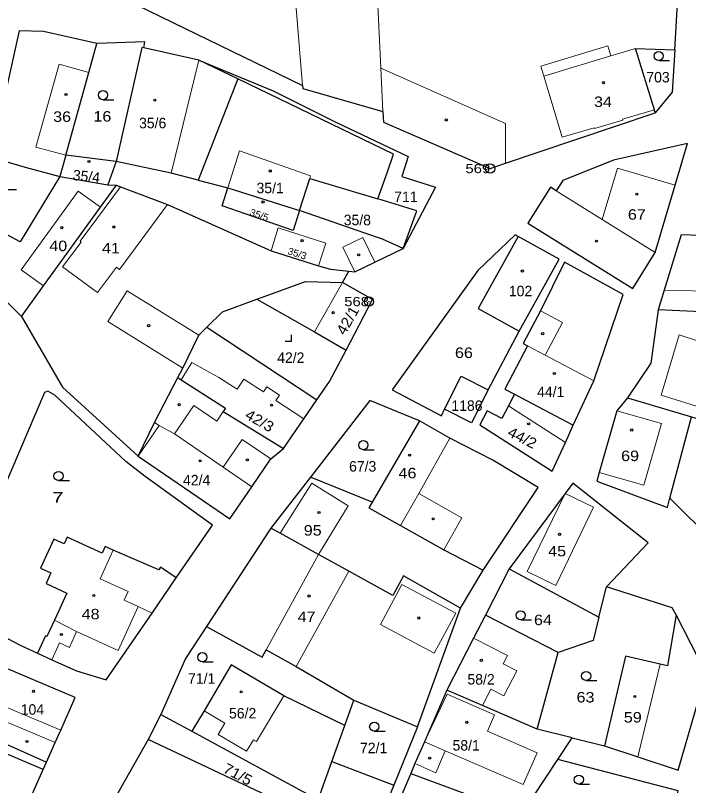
# Model space of a CAD drawing. Extents: x -758887 to -754328, y -1031688 to -1029144.
# Drawn here: x -756515.3 to -756406, y -1030560.6 to -1030435.5 of the extents above; entities that cross this region are included whole.
import ezdxf
from ezdxf.enums import TextEntityAlignment as Align

# ---------------------------------------------------------------- set-up
doc = ezdxf.new("R2010")
doc.units = 0
doc.header["$LTSCALE"] = 0.68
for name, color, linetype, lineweight in [('1', 7, 'Continuous', 25), ('3', 7, 'Continuous', 25), ('4', 7, 'Continuous', 13), ('5', 7, 'Continuous', 25), ('8', 7, 'Continuous', 25)]:
    doc.layers.add(name, color=color, linetype=linetype, lineweight=lineweight)
doc.layers.add('2', color=7, linetype='Continuous')

msp = doc.modelspace()

# ---------------------------------------------------------------- linework, layer by layer
at = {"layer": '1'}
for p, q in [((-756479.24, -1030445.82), (-756485.68, -1030462.26)), ((-756508.15, -1030461.68), (-756500.31, -1030462.99)), ((-756484.24, -1030486.15), (-756466.38, -1030497.95)), ((-756438.56, -1030496.32), (-756433.52, -1030486.81)), ((-756434.29, -1030497.04), (-756424.76, -1030502.04)), ((-756409.04, -1030513.92), (-756405.56, -1030500.72)), ((-756443.05, -1030531.77), (-756439.39, -1030525.61)), ((-756435.14, -1030525.41), (-756439.01, -1030532.91)), ((-756461.87, -1030550.85), (-756460.39, -1030546.71)), ((-756491.72, -1030549.05), (-756493.78, -1030553.1)), ((-756450.04, -1030551.07), (-756453.91, -1030560.56)), ((-756467.23, -1030565.61), (-756493.78, -1030553.1)), ((-756424.9, -1030552.84), (-756419.67, -1030554.14)), ((-756510.82, -1030558), (-756510.29, -1030556.81)), ((-756463.96, -1030556.71), (-756453.91, -1030560.56)), ((-756451.15, -1030558.65), (-756454.23, -1030565.79))]:
    msp.add_line(p, q, dxfattribs=at)
for points in [[(-756408.26, -1030441.06), (-756407.42, -1030426.91), (-756407.17, -1030422.67)], [(-756510.06, -1030431.65), (-756502.06, -1030431), (-756501.36, -1030430.94), (-756468.7, -1030446.88), (-756468.66, -1030447.38), (-756455.66, -1030451.12), (-756455.58, -1030452.82), (-756438.25, -1030460.37), (-756435.76, -1030459.47), (-756424.35, -1030455.63), (-756411.42, -1030451.34)], [(-756502.12, -1030440.04), (-756510.76, -1030438.1), (-756514.76, -1030437.98), (-756519.35, -1030458.53)], [(-756494.51, -1030440.77), (-756494.32, -1030439.78), (-756502.12, -1030440.04)], [(-756507.18, -1030458.21), (-756503.44, -1030444.77), (-756502.12, -1030440.04)], [(-756494.51, -1030440.77), (-756494.8, -1030440.7), (-756498.97, -1030459.24)], [(-756479.24, -1030445.82), (-756485.55, -1030442.78), (-756494.51, -1030440.77)], [(-756411.42, -1030451.34), (-756411.57, -1030450.84), (-756414.63, -1030440.87), (-756408.26, -1030441.06)], [(-756408.26, -1030441.06), (-756408.67, -1030447.94), (-756411.42, -1030451.34)], [(-756485.55, -1030442.78), (-756473.5, -1030447.72), (-756463.29, -1030452.83), (-756451.58, -1030458.43), (-756452.6, -1030461.64), (-756447.12, -1030463.38), (-756452.38, -1030473.38)], [(-756456.49, -1030465.29), (-756454.94, -1030460.89), (-756453.94, -1030458.02), (-756479.24, -1030445.82)], [(-756519.35, -1030458.53), (-756513.77, -1030460.12), (-756508.15, -1030461.68)], [(-756498.97, -1030459.24), (-756507.18, -1030458.21), (-756508.15, -1030461.68)], [(-756485.68, -1030462.26), (-756490.05, -1030461.14), (-756498.97, -1030459.24), (-756500.31, -1030462.99), (-756498.95, -1030463.07)], [(-756508.15, -1030461.68), (-756514.57, -1030472.26), (-756518.98, -1030469.92), (-756522.95, -1030467.81)], [(-756485.68, -1030462.26), (-756480.83, -1030463.51), (-756469.2, -1030467.18)], [(-756469.2, -1030467.18), (-756467.53, -1030461.96), (-756456.49, -1030465.29)], [(-756514.38, -1030484.42), (-756510.77, -1030479.43), (-756501.53, -1030466.64), (-756498.95, -1030463.07)], [(-756498.95, -1030463.07), (-756498.25, -1030463.33), (-756490.65, -1030466.23), (-756473.82, -1030473.71), (-756466.1, -1030476.17), (-756464.15, -1030476.71), (-756461.19, -1030477.06)], [(-756469.2, -1030467.18), (-756470.24, -1030470.42), (-756481.76, -1030466.45), (-756480.83, -1030463.51)], [(-756452.38, -1030473.38), (-756450.13, -1030467.23), (-756456.49, -1030465.29)], [(-756452.38, -1030473.38), (-756455.72, -1030471.84), (-756458.44, -1030470.9), (-756469.2, -1030467.18)], [(-756522.95, -1030467.81), (-756526.37, -1030474.26), (-756522.4, -1030476.37), (-756514.38, -1030484.42)], [(-756433.68, -1030471.41), (-756434.18, -1030471.13), (-756440.26, -1030476.91), (-756454.15, -1030496.31), (-756446.16, -1030500.53), (-756445.63, -1030499.48)], [(-756375.85, -1030484.87), (-756388.84, -1030471.72), (-756397.68, -1030471.45), (-756407.23, -1030471.16), (-756409.98, -1030480.1), (-756410.97, -1030483.3)], [(-756433.68, -1030471.41), (-756440.17, -1030483.13), (-756433.52, -1030486.81)], [(-756433.52, -1030486.81), (-756427.03, -1030475.09), (-756433.68, -1030471.41)], [(-756461.19, -1030477.06), (-756460.21, -1030477.17), (-756456.97, -1030475.6), (-756452.38, -1030473.38)], [(-756424.76, -1030502.04), (-756421.43, -1030494.83), (-756416.62, -1030480.84), (-756426.15, -1030475.57), (-756430.07, -1030483.48), (-756432.88, -1030488.78), (-756432.16, -1030489.16), (-756435.88, -1030496.2), (-756434.29, -1030497.04)], [(-756476.13, -1030481.61), (-756468.22, -1030478.73), (-756462.22, -1030478.88), (-756461.19, -1030477.06)], [(-756461.65, -1030489.85), (-756457.34, -1030481.66), (-756462.22, -1030478.88)], [(-756484.24, -1030486.15), (-756481.7, -1030483.64), (-756476.13, -1030481.61)], [(-756476.13, -1030481.61), (-756466.79, -1030486.92), (-756461.65, -1030489.85)], [(-756384.93, -1030481.41), (-756388.28, -1030481.31), (-756388.37, -1030484.34), (-756399.29, -1030483.84), (-756410.97, -1030483.3)], [(-756410.97, -1030483.3), (-756412.16, -1030491.99), (-756415.96, -1030497.63), (-756405.56, -1030500.72), (-756392.11, -1030504.7)], [(-756514.38, -1030484.42), (-756507.71, -1030495.87), (-756495.38, -1030507.08)], [(-756488.98, -1030494.33), (-756488.16, -1030492.77), (-756485.56, -1030487.45), (-756484.24, -1030486.15)], [(-756466.38, -1030497.95), (-756464.32, -1030494.94), (-756461.65, -1030489.85)], [(-756495.38, -1030507.08), (-756492.73, -1030501.62), (-756488.98, -1030494.33)], [(-756488.98, -1030494.33), (-756488.41, -1030494.7), (-756481.22, -1030499.32), (-756481.59, -1030499.86), (-756471.78, -1030505.85)], [(-756445.63, -1030499.48), (-756442.94, -1030494.12), (-756438.56, -1030496.32)], [(-756489.22, -1030526.88), (-756483.33, -1030518.31), (-756494.29, -1030510.42), (-756497.43, -1030507.94), (-756508.95, -1030497.19), (-756510.09, -1030496.54), (-756510.6, -1030496.77), (-756525.69, -1030531.93), (-756514.55, -1030537.82), (-756511.73, -1030539.11)], [(-756438.56, -1030496.32), (-756441.25, -1030501.68), (-756445.63, -1030499.48)], [(-756434.29, -1030497.04), (-756435.26, -1030498.92), (-756436.32, -1030500.96), (-756438.73, -1030499.71), (-756439.91, -1030501.98), (-756428.16, -1030509.54), (-756426.01, -1030504.89), (-756424.76, -1030502.04)], [(-756471.78, -1030505.85), (-756468.5, -1030501.05), (-756466.38, -1030497.95)], [(-756449.74, -1030501.36), (-756457.78, -1030498.04), (-756467.42, -1030510.49)], [(-756415.96, -1030497.63), (-756417.68, -1030499.73), (-756420.52, -1030509.76), (-756420.92, -1030511.16), (-756409.44, -1030515.43), (-756409.04, -1030513.92)], [(-756439.39, -1030525.61), (-756430.47, -1030512.2), (-756437.81, -1030507.76), (-756444.78, -1030504.16), (-756449.74, -1030501.36), (-756457.43, -1030514.59)], [(-756495.38, -1030507.08), (-756480.52, -1030517.25), (-756476.96, -1030512.05), (-756473.88, -1030507.55), (-756471.78, -1030505.85)], [(-756457.43, -1030514.59), (-756467.42, -1030510.49), (-756473.86, -1030518.78)], [(-756419.36, -1030528.34), (-756412.57, -1030521.18), (-756424.83, -1030511.5), (-756426.06, -1030513.15), (-756435.14, -1030525.41)], [(-756457.43, -1030514.59), (-756457.92, -1030515.46), (-756452.79, -1030518.36), (-756445.77, -1030522.31), (-756439.39, -1030525.61)], [(-756409.04, -1030513.92), (-756401.99, -1030520.93), (-756385.48, -1030517.02)], [(-756443.05, -1030531.77), (-756449.16, -1030528.32), (-756452.3, -1030526.55), (-756454.04, -1030529.71), (-756461.19, -1030525.77), (-756466.1, -1030523.06), (-756472.37, -1030519.6), (-756473.86, -1030518.78), (-756484.31, -1030534.76)], [(-756489.22, -1030526.88), (-756491.78, -1030525.13), (-756492.06, -1030525.54), (-756499.47, -1030522.36), (-756500.74, -1030521.78), (-756501.24, -1030522.87), (-756506.93, -1030520.27), (-756507.42, -1030521.34), (-756509.11, -1030520.58), (-756511.26, -1030525.31), (-756509.58, -1030526.07), (-756510.37, -1030527.8), (-756507, -1030529.34), (-756509.01, -1030533.75), (-756510.22, -1030536.39), (-756510.44, -1030536.29), (-756511.73, -1030539.11)], [(-756435.14, -1030525.41), (-756420.57, -1030533.26), (-756419.36, -1030528.34)], [(-756511.73, -1030539.11), (-756509.41, -1030540.16), (-756505.44, -1030541.97), (-756500.61, -1030543.43), (-756493.14, -1030532.57), (-756489.22, -1030526.88)], [(-756408.06, -1030532.89), (-756408.67, -1030531.71), (-756419.36, -1030528.34)], [(-756460.39, -1030546.71), (-756450.04, -1030551.07), (-756443.05, -1030531.77)], [(-756439.01, -1030532.91), (-756440.94, -1030536.65), (-756445.29, -1030545.09)], [(-756430.63, -1030551.42), (-756427.21, -1030539), (-756439.01, -1030532.91)], [(-756420.57, -1030533.26), (-756421.51, -1030537.06), (-756427.21, -1030539)], [(-756408.06, -1030532.89), (-756409.44, -1030541.17), (-756410.61, -1030540.89), (-756416.26, -1030539.57), (-756419.67, -1030554.14)], [(-756419.67, -1030554.14), (-756414.24, -1030555.94), (-756407.72, -1030558.1), (-756403.18, -1030542.41), (-756408.06, -1030532.89)], [(-756484.31, -1030534.76), (-756487.7, -1030539.95), (-756491.72, -1030549.05), (-756486.69, -1030551.79)], [(-756484.31, -1030534.76), (-756475.29, -1030539.74), (-756474.63, -1030538.55), (-756469.73, -1030541.25), (-756460.39, -1030546.71)], [(-756510.29, -1030556.81), (-756508.87, -1030553.61), (-756507.98, -1030551.62), (-756505.62, -1030546.3), (-756518.46, -1030540.86), (-756521.83, -1030539.62), (-756523.99, -1030538.82), (-756527.18, -1030545.83)], [(-756461.87, -1030550.85), (-756471.76, -1030546.01), (-756480.28, -1030540.97), (-756484.71, -1030548.45), (-756486.69, -1030551.79)], [(-756527.18, -1030545.83), (-756523.16, -1030547.54), (-756516.83, -1030550.23), (-756518.19, -1030553.3), (-756510.29, -1030556.81)], [(-756445.29, -1030545.09), (-756448.93, -1030553.51), (-756450.46, -1030557.04), (-756451.15, -1030558.65), (-756433.14, -1030565.31), (-756427.23, -1030556.37), (-756424.9, -1030552.84), (-756430.63, -1030551.42)], [(-756430.63, -1030551.42), (-756439.49, -1030547.59), (-756445.29, -1030545.09)], [(-756515.42, -1030568.35), (-756510.82, -1030558), (-756529.65, -1030550)], [(-756486.69, -1030551.79), (-756466.18, -1030562.91), (-756463.96, -1030556.71), (-756461.87, -1030550.85)], [(-756493.78, -1030553.1), (-756508.46, -1030579.07), (-756475.62, -1030587.14)], [(-756410.96, -1030579.14), (-756407.69, -1030561.45), (-756427.23, -1030556.37)], [(-756453.91, -1030560.56), (-756456.58, -1030567.12), (-756460.05, -1030579.99), (-756464.55, -1030590.48), (-756475.62, -1030587.14)]]:
    msp.add_lwpolyline(points, dxfattribs=at)
msp.add_lwpolyline([(-756428.46, -1030463.42), (-756432.1, -1030469.26), (-756415.08, -1030479.86), (-756411.44, -1030474.02), (-756408.21, -1030463.09), (-756406.21, -1030456.32), (-756418.22, -1030459.02), (-756426.46, -1030462.31), (-756427.52, -1030464.01)], close=True, dxfattribs=at)
at = {"layer": '3'}
for p, q in [((-756410.873, -1030442.83), (-756409.123, -1030442.83)), ((-756501.113, -1030449.19), (-756499.363, -1030449.19)), ((-756516.923, -1030463.78), (-756515.173, -1030463.78)), ((-756458.833, -1030506.04), (-756457.083, -1030506.04)), ((-756508.333, -1030511.07), (-756506.583, -1030511.07)), ((-756433.283, -1030533.69), (-756431.533, -1030533.69)), ((-756484.983, -1030540.5), (-756483.233, -1030540.5)), ((-756422.653, -1030543.55), (-756420.903, -1030543.55)), ((-756457.063, -1030551.79), (-756455.313, -1030551.79)), ((-756423.843, -1030560.39), (-756422.093, -1030560.39))]:
    msp.add_line(p, q, dxfattribs=at)
msp.add_lwpolyline([(-756471.521, -1030488.39), (-756470.52, -1030488.39), (-756470.52, -1030487.39)], dxfattribs=at)
for centre in [(-756410.8729, -1030442.0798), (-756501.1129, -1030448.4398), (-756458.8329, -1030505.2898), (-756508.3329, -1030510.3198), (-756433.2829, -1030532.9398), (-756484.9829, -1030539.7498), (-756422.6529, -1030542.7998), (-756457.0629, -1030551.0398), (-756423.8429, -1030559.6398)]:
    msp.add_circle(centre, 0.75, dxfattribs=at)
at = {"layer": '4'}
for p, q in [((-756455.99, -1030444.05), (-756456.9, -1030424.4)), ((-756414.63, -1030440.87), (-756418.65, -1030442.08)), ((-756429.52, -1030445.35), (-756418.65, -1030442.08)), ((-756485.55, -1030442.78), (-756490.05, -1030461.14)), ((-756455.66, -1030451.12), (-756455.99, -1030444.05)), ((-756429.52, -1030445.35), (-756430.01, -1030443.72)), ((-756426.55, -1030455.28), (-756429.52, -1030445.35)), ((-756411.57, -1030450.84), (-756416.75, -1030452.37)), ((-756416.7, -1030452.52), (-756416.75, -1030452.37)), ((-756421.3, -1030453.89), (-756416.7, -1030452.52)), ((-756426.55, -1030455.28), (-756421.35, -1030453.75)), ((-756421.35, -1030453.75), (-756421.3, -1030453.89)), ((-756512, -1030456.87), (-756507.18, -1030458.21)), ((-756480.83, -1030463.51), (-756478.93, -1030457.51)), ((-756478.93, -1030457.51), (-756467.41, -1030461.57)), ((-756420.05, -1030468.66), (-756417.58, -1030460.32)), ((-756417.58, -1030460.32), (-756408.21, -1030463.09)), ((-756467.41, -1030461.57), (-756467.53, -1030461.96)), ((-756498.25, -1030463.33), (-756504.85, -1030472.19)), ((-756514.39, -1030476.82), (-756505.15, -1030464.02)), ((-756505.15, -1030464.02), (-756501.53, -1030466.64)), ((-756420.05, -1030468.66), (-756427.52, -1030464.01)), ((-756490.65, -1030466.23), (-756498.46, -1030476.75)), ((-756411.44, -1030474.02), (-756420.05, -1030468.66)), ((-756472.65, -1030470.02), (-756473.82, -1030473.71)), ((-756464.93, -1030472.47), (-756472.65, -1030470.02)), ((-756504.69, -1030472.31), (-756507.67, -1030476.33)), ((-756504.85, -1030472.19), (-756504.69, -1030472.31)), ((-756462.17, -1030473.12), (-756458.93, -1030471.55)), ((-756458.93, -1030471.55), (-756456.97, -1030475.6)), ((-756466.1, -1030476.17), (-756464.93, -1030472.47)), ((-756462.17, -1030473.12), (-756460.21, -1030477.17)), ((-756514.39, -1030476.82), (-756510.77, -1030479.43)), ((-756507.67, -1030476.33), (-756502.01, -1030480.53)), ((-756498.94, -1030476.4), (-756502.01, -1030480.53)), ((-756498.46, -1030476.75), (-756498.94, -1030476.4)), ((-756462.22, -1030478.88), (-756466.79, -1030486.92)), ((-756500.31, -1030485.23), (-756497.2, -1030480.21)), ((-756497.2, -1030480.21), (-756485.56, -1030487.45)), ((-756409.98, -1030480.1), (-756399.14, -1030480.43)), ((-756426.5, -1030485.37), (-756430.07, -1030483.48)), ((-756488.16, -1030492.77), (-756500.31, -1030485.23)), ((-756426.5, -1030485.37), (-756429.3, -1030490.67)), ((-756432.16, -1030489.16), (-756429.3, -1030490.67)), ((-756421.43, -1030494.83), (-756429.3, -1030490.67)), ((-756410.46, -1030497.18), (-756401.78, -1030499.91)), ((-756486.34, -1030498.84), (-756489.51, -1030503.47)), ((-756482.63, -1030501.39), (-756486.34, -1030498.84)), ((-756481.59, -1030499.86), (-756482.63, -1030501.39)), ((-756435.26, -1030498.92), (-756434.04, -1030499.71)), ((-756426.01, -1030504.89), (-756434.04, -1030499.71)), ((-756410.42, -1030501.79), (-756417.68, -1030499.73)), ((-756491.99, -1030502.13), (-756495.38, -1030507.08)), ((-756492.73, -1030501.62), (-756491.99, -1030502.13)), ((-756489.51, -1030503.47), (-756491.99, -1030502.13)), ((-756413.26, -1030511.82), (-756410.42, -1030501.79)), ((-756489.51, -1030503.47), (-756481.58, -1030508.89)), ((-756481.58, -1030508.89), (-756478.51, -1030504.39)), ((-756478.51, -1030504.39), (-756473.88, -1030507.55)), ((-756444.78, -1030504.16), (-756449.84, -1030513.13)), ((-756481.58, -1030508.89), (-756476.96, -1030512.05)), ((-756420.52, -1030509.76), (-756413.26, -1030511.82)), ((-756452.79, -1030518.36), (-756449.84, -1030513.13)), ((-756449.84, -1030513.13), (-756442.83, -1030517.09)), ((-756432.21, -1030525.85), (-756426.06, -1030513.15)), ((-756426.06, -1030513.15), (-756421.44, -1030515.39)), ((-756442.83, -1030517.09), (-756445.77, -1030522.31)), ((-756499.47, -1030522.36), (-756501.59, -1030527)), ((-756474.63, -1030538.55), (-756466.1, -1030523.06)), ((-756469.73, -1030541.25), (-756461.19, -1030525.77)), ((-756501.59, -1030527), (-756497.04, -1030529.08)), ((-756456.05, -1030534.45), (-756452.56, -1030527.92)), ((-756443.83, -1030532.58), (-756452.56, -1030527.92)), ((-756497.04, -1030529.08), (-756497.68, -1030530.49)), ((-756497.68, -1030530.49), (-756495.41, -1030531.53)), ((-756495.41, -1030531.53), (-756498.67, -1030538.67)), ((-756493.14, -1030532.57), (-756495.41, -1030531.53)), ((-756447.31, -1030539.11), (-756443.83, -1030532.58)), ((-756505.4, -1030535.6), (-756509.01, -1030533.75)), ((-756456.05, -1030534.45), (-756447.31, -1030539.11)), ((-756508.16, -1030537.44), (-756509.41, -1030540.16)), ((-756435.42, -1030539.49), (-756440.94, -1030536.65)), ((-756436.11, -1030540.82), (-756435.42, -1030539.49)), ((-756433.89, -1030541.96), (-756436.11, -1030540.82)), ((-756414.24, -1030555.94), (-756410.61, -1030540.89)), ((-756436, -1030546.05), (-756433.89, -1030541.96)), ((-756439.49, -1030547.59), (-756438.13, -1030544.95)), ((-756438.13, -1030544.95), (-756436, -1030546.05)), ((-756507.98, -1030551.62), (-756520.73, -1030546.22)), ((-756476.17, -1030553.45), (-756471.76, -1030546.01)), ((-756445.25, -1030545.76), (-756448.93, -1030553.51)), ((-756481.32, -1030550.47), (-756484.71, -1030548.45)), ((-756516.83, -1030550.23), (-756508.87, -1030553.61)), ((-756482.43, -1030552.28), (-756481.32, -1030550.47)), ((-756482.43, -1030552.28), (-756477.8, -1030555.02)), ((-756477.8, -1030555.02), (-756476.69, -1030553.15)), ((-756476.69, -1030553.15), (-756476.17, -1030553.45)), ((-756445.54, -1030554.97), (-756448.93, -1030553.51)), ((-756445.54, -1030554.97), (-756447.06, -1030558.51)), ((-756432.86, -1030560.45), (-756445.54, -1030554.97)), ((-756447.06, -1030558.51), (-756450.46, -1030557.04))]:
    msp.add_line(p, q, dxfattribs=at)
for points in [[(-756468.7, -1030446.88), (-756470.53, -1030425.03), (-756456.9, -1030424.4)], [(-756430.01, -1030443.72), (-756419.14, -1030440.45), (-756418.65, -1030442.08)], [(-756512, -1030456.87), (-756508.25, -1030443.43), (-756503.44, -1030444.77)], [(-756435.76, -1030459.47), (-756435.76, -1030453.07), (-756455.99, -1030444.05)], [(-756410.46, -1030497.18), (-756407.56, -1030487.4), (-756403.9, -1030488.59)], [(-756468.5, -1030501.05), (-756473.03, -1030498.04), (-756472.47, -1030497.18), (-756474.51, -1030495.83), (-756475.07, -1030496.63), (-756478.27, -1030494.58), (-756479.32, -1030496.21), (-756482.3, -1030494.32), (-756486.7, -1030491.88), (-756488.41, -1030494.7)], [(-756466.1, -1030523.06), (-756461.32, -1030515.18), (-756467.18, -1030511.48), (-756472.37, -1030519.6)], [(-756432.21, -1030525.85), (-756427.59, -1030528.09), (-756421.44, -1030515.39)], [(-756498.67, -1030538.67), (-756505.4, -1030535.6), (-756506.57, -1030538.16), (-756508.16, -1030537.44)], [(-756445.25, -1030545.76), (-756437.54, -1030549.09), (-756438.7, -1030551.77), (-756430.62, -1030555.26), (-756432.86, -1030560.45)]]:
    msp.add_lwpolyline(points, dxfattribs=at)
at = {"layer": '5'}
for centre in [(-756419.8368, -1030446.4192), (-756507.1168, -1030448.3492), (-756492.6968, -1030449.2692), (-756445.3668, -1030452.4692), (-756503.4068, -1030459.2292), (-756473.9568, -1030460.7692), (-756414.4268, -1030464.5292), (-756475.1268, -1030465.8092), (-756507.8068, -1030469.9692), (-756499.3568, -1030469.8692), (-756468.7868, -1030472.0892), (-756420.9768, -1030472.1692), (-756459.5868, -1030474.3892), (-756433.0068, -1030477.0192), (-756463.7368, -1030483.7892), (-756493.7068, -1030485.8892), (-756429.7068, -1030487.1992), (-756427.8068, -1030493.6592), (-756488.7468, -1030498.7292), (-756473.7468, -1030498.8092), (-756431.9868, -1030501.8392), (-756415.2568, -1030502.8392), (-756451.3268, -1030506.9292), (-756485.3268, -1030507.8592), (-756477.6768, -1030507.6892), (-756466.0368, -1030516.2392), (-756447.4968, -1030517.2792), (-756426.9668, -1030519.7792), (-756502.5968, -1030529.7292), (-756467.6568, -1030529.8192), (-756449.8168, -1030533.3692), (-756507.8768, -1030536.0592), (-756439.6668, -1030540.2592), (-756512.3968, -1030545.2992), (-756478.6768, -1030545.3692), (-756414.7468, -1030546.1292), (-756442.0268, -1030550.3392), (-756513.4568, -1030553.4492), (-756448.0768, -1030556.1592)]:
    msp.add_circle(centre, 0.175, dxfattribs=at)
at = {"layer": '8'}
for centre, radius in [((-756438.24, -1030460.3698), 0.75), ((-756438.24, -1030460.3698), 0.03), ((-756457.92, -1030481.9798), 0.75), ((-756457.92, -1030481.9798), 0.03)]:
    msp.add_circle(centre, radius, dxfattribs=at)

# ---------------------------------------------------------------- texts
at = {"layer": '2'}
for s, p in [('703', (-756410.979, -1030446.38)), ('35/6', (-756493.05, -1030453.83)), ('35/1', (-756473.97, -1030464.38)), ('711', (-756451.929, -1030465.8)), ('35/8', (-756459.81, -1030469.58)), ('102', (-756433.309, -1030481.12)), ('42/2', (-756470.62, -1030491.94)), ('44/1', (-756428.4, -1030497.48)), ('1186', (-756442.01, -1030499.73)), ('67/3', (-756458.94, -1030509.59)), ('42/4', (-756485.91, -1030511.83)), ('71/1', (-756485.09, -1030544.05)), ('58/2', (-756439.72, -1030544.19)), ('104', (-756512.579, -1030549.09)), ('56/2', (-756478.44, -1030549.7)), ('72/1', (-756457.17, -1030555.34)), ('58/1', (-756442.14, -1030554.91))]:
    msp.add_text(s, height=1.7, dxfattribs=at).set_placement(p, align=Align.CENTER)
for s, width, p in [('34', 1.15, (-756419.92, -1030450.37)), ('36', 1.15, (-756507.76, -1030452.79)), ('16', 1.15, (-756501.22, -1030452.74)), ('67', 1.15, (-756414.42, -1030468.68)), ('40', 1.15, (-756508.39, -1030473.78)), ('41', 1.15, (-756499.82, -1030474.14)), ('66', 1.15, (-756442.5, -1030491.14)), ('69', 1.15, (-756415.52, -1030507.89)), ('46', 1.15, (-756451.67, -1030510.69)), ('7', 1.45, (-756508.44, -1030514.62)), ('95', 1.15, (-756467.06, -1030519.99)), ('45', 1.15, (-756427.36, -1030523.36)), ('48', 1.15, (-756503.13, -1030533.6)), ('47', 1.15, (-756468.06, -1030534.04)), ('64', 1.15, (-756429.67, -1030534.54)), ('63', 1.15, (-756422.76, -1030547.1)), ('59', 1.15, (-756415.08, -1030550.36))]:
    msp.add_text(s, height=1.7, dxfattribs=dict(at, width=width)).set_placement(p, align=Align.CENTER)
msp.add_text('35/4', height=1.7, rotation=354, dxfattribs=at).set_placement((-756503.8888, -1030462.4715), align=Align.CENTER)
for s, height, rotation, width, p in [('35/5', 1.14, 341, 1.05, (-756475.9211, -1030468.441)), ('35/3', 1.14, 342, 1.05, (-756469.7486, -1030474.7194)), ('42/1', 1.7, 60, 1.1, (-756460.65, -1030485.461)), ('42/3', 1.7, 330, 1.1, (-756476.111, -1030502.059)), ('44/2', 1.7, 333, 1.1, (-756433.4079, -1030504.8475)), ('71/5', 1.7, 332, 1.1, (-756479.6221, -1030559.5217))]:
    msp.add_text(s, height=height, rotation=rotation, dxfattribs=dict(at, width=width)).set_placement(p, align=Align.CENTER)
at = {"layer": '8', "width": 1.2}
for s, p in [('569', (-756438.24, -1030461.12)), ('568', (-756457.92, -1030482.73))]:
    msp.add_text(s, height=1.5, dxfattribs=at).set_placement(p, align=Align.RIGHT)

doc.saveas('drawing.dxf')
